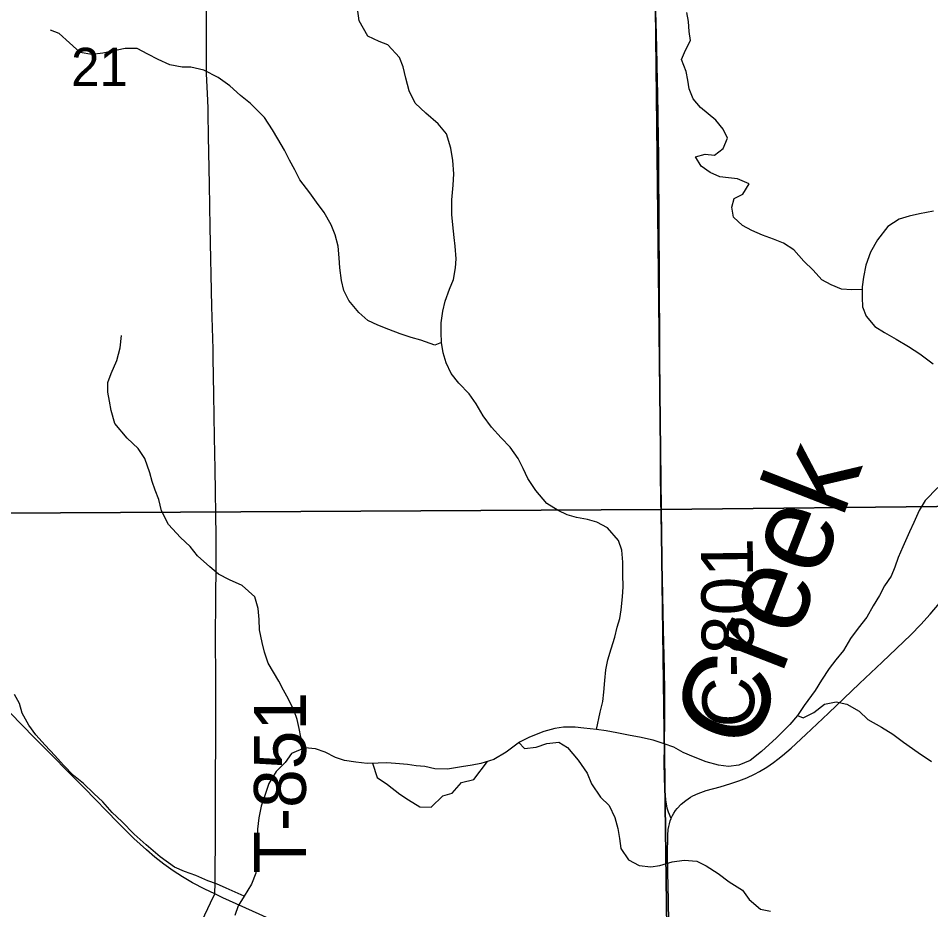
# Model space of a CAD drawing. Extents: x 1874609 to 2204689, y 815661 to 1281160.
# Drawn here: x 2025118 to 2030390, y 1065160 to 1070308 of the extents above; entities that cross this region are included whole.
import ezdxf

# ---------------------------------------------------------------- set-up
doc = ezdxf.new("R2010")
doc.units = 0
for name, color, linetype in [('GM_X_County_Road', 7, 'Continuous'), ('GM_X_County_Road_Text', 7, 'Continuous'), ('GM_X_Minor_River', 7, 'Continuous'), ('GM_X_Minor_River_Text', 7, 'Continuous'), ('GM_X_Section', 7, 'Continuous'), ('GM_X_Section_Text', 7, 'Continuous'), ('GM_X_State_Route', 7, 'Continuous'), ('GM_X_Township_Road', 7, 'Continuous'), ('GM_X_Township_Road_Text', 7, 'Continuous')]:
    doc.layers.add(name, color=color, linetype=linetype)

msp = doc.modelspace()

# ---------------------------------------------------------------- linework, layer by layer
at = {"layer": 'GM_X_County_Road'}
msp.add_lwpolyline([(2028889.9, 1065686.4), (2028876.2, 1065723.5), (2028867.4, 1065747), (2028860.1, 1065795.2), (2028855.4, 1065844.3), (2028852.1, 1065909.8), (2028851.2, 1066024.2), (2028851.9, 1066089.5), (2028854.2, 1066286.3), (2028853.4, 1066417.4), (2028851.6, 1066548.6), (2028847, 1066777.8), (2028840.5, 1067072.6), (2028835, 1067318.4), (2028832.8, 1067449.6), (2028831.5, 1067515.1), (2028829.6, 1067695.3), (2028828.4, 1067810.1), (2028828, 1068023.4), (2028827.4, 1068187.4), (2028825.8, 1068318.6), (2028824.6, 1068499), (2028823.3, 1068712.3), (2028823, 1068892.8), (2028822.2, 1069040.3), (2028821, 1069204.3), (2028819.8, 1069384.8), (2028819.3, 1069515.9), (2028817.9, 1069614.3), (2028815.1, 1069745.3), (2028812.9, 1069876.5), (2028811.7, 1069942), (2028807.4, 1070138.4), (2028803.4, 1070285.9), (2028800.7, 1070400.8)], dxfattribs=at)
at = {"layer": 'GM_X_Minor_River'}
for points in [[(2028459.2, 1066201.1), (2028480.4, 1066301.6), (2028496, 1066362), (2028501.5, 1066416.2), (2028507, 1066484.5), (2028512.5, 1066544.7), (2028524.1, 1066603), (2028543.6, 1066667.3), (2028565.1, 1066733.8), (2028578.7, 1066792.1), (2028594.3, 1066842.3), (2028601.9, 1066892.6), (2028609.3, 1066966.9), (2028612.9, 1067025.1), (2028612.3, 1067095.3), (2028611.7, 1067167.6), (2028605.1, 1067235.8), (2028586.6, 1067291.8), (2028523.8, 1067365.6), (2028461.4, 1067397.2), (2028407.1, 1067412.9), (2028342.8, 1067424.5), (2028290.5, 1067440.1), (2028238.2, 1067465.8), (2028171.6, 1067505.5), (2028108.8, 1067581.3), (2028062.1, 1067651.1), (2028035.6, 1067707.1), (2028007, 1067765.1), (2027960.3, 1067831), (2027907.7, 1067884.8), (2027853.1, 1067946.6), (2027804.4, 1068012.5), (2027763.7, 1068082.4), (2027723.1, 1068138.3), (2027664.4, 1068200.1), (2027619.8, 1068255.9), (2027591.3, 1068317.9), (2027572.7, 1068376), (2027564.2, 1068436.1), (2027561.7, 1068494.3), (2027561.3, 1068548.5), (2027570.8, 1068616.8), (2027584.3, 1068675.1), (2027609.8, 1068743.5), (2027633.4, 1068799.9), (2027644.9, 1068866.2), (2027648.5, 1068918.4), (2027641.9, 1068992.6), (2027637.5, 1069042.7), (2027628.9, 1069114.9), (2027624.3, 1069175.1), (2027623.6, 1069259.4), (2027631, 1069343.7), (2027634.5, 1069409.9), (2027629.8, 1069486.2), (2027617.2, 1069558.3), (2027592.4, 1069640.4), (2027543.8, 1069698.2), (2027473.1, 1069759.9), (2027412.5, 1069817.7), (2027377.8, 1069889.7), (2027357.1, 1069961.8), (2027342.5, 1070027.9), (2027322, 1070081.9), (2027253.2, 1070155.6), (2027202.9, 1070173.3), (2027138.5, 1070205), (2027087.6, 1070292.9), (2027079, 1070365.1)], [(2029994.4, 1068741.4), (2029934.3, 1068740), (2029874.3, 1068744.4), (2029814.3, 1068768.9), (2029760.3, 1068797.3), (2029710.6, 1068853.8), (2029656.8, 1068906.3), (2029599, 1068970.9), (2029539.1, 1069009.4), (2029481.1, 1069031.8), (2029419.2, 1069056.3), (2029357.2, 1069082.8), (2029303.2, 1069111.3), (2029251.4, 1069159.7), (2029241.7, 1069218), (2029254, 1069268.1), (2029304.2, 1069291.8), (2029340.6, 1069351.8), (2029274.6, 1069380.3), (2029222.6, 1069386.6), (2029172.5, 1069393), (2029116.6, 1069417.4), (2029064.7, 1069453.9), (2029030.9, 1069508.3), (2029087.1, 1069523.9), (2029141.1, 1069517.6), (2029191.4, 1069555.4), (2029215.8, 1069615.4), (2029192, 1069667.7), (2029148.2, 1069720.2), (2029060.5, 1069793), (2029018.7, 1069843.4), (2028994.9, 1069899.7), (2028987.2, 1069949.9), (2028977.4, 1070000.2), (2028949.8, 1070070.6), (2028974.1, 1070124.6), (2029002.4, 1070180.6), (2028994.7, 1070230.8), (2028991, 1070289), (2028981.3, 1070341.2)], [(2027564.2, 1068436.1), (2027526.2, 1068419.8), (2027443.7, 1068449.3), (2027389.4, 1068464.9), (2027325.1, 1068486.5), (2027258.7, 1068510.1), (2027196.3, 1068535.8), (2027137.9, 1068563.4), (2027085.4, 1068609.2), (2027028.6, 1068679), (2027000.1, 1068735), (2026985.6, 1068793.1), (2026976.9, 1068867.2), (2026972.4, 1068925.4), (2026965.9, 1068991.6), (2026949.3, 1069057.7), (2026926.8, 1069115.7), (2026886.1, 1069185.7), (2026841.4, 1069245.5), (2026802.9, 1069299.4), (2026746.1, 1069375.3), (2026715.5, 1069433.2), (2026685, 1069489.2), (2026656.4, 1069547.2), (2026617.8, 1069611.1), (2026587.3, 1069663.1), (2026540.5, 1069735), (2026459.6, 1069816.6), (2026403.1, 1069862.4), (2026340.4, 1069918.1), (2026273.9, 1069965.8), (2026191.3, 1070009.3), (2026114.9, 1070024.8), (2026064.7, 1070026.4), (2025994.4, 1070040), (2025926, 1070069.6), (2025867.5, 1070101.2), (2025805.1, 1070132.9), (2025736.9, 1070134.4), (2025606.7, 1070107.3), (2025542.6, 1070098.8), (2025476.3, 1070110.4), (2025413.6, 1070166.1), (2025355, 1070219.8), (2025304.7, 1070239.5)], [(2030406.4, 1069193.7), (2030326.3, 1069179.1), (2030266.3, 1069164.6), (2030208.2, 1069148.1), (2030142.4, 1069105.5), (2030082.8, 1069028.8), (2030043.3, 1068958.2), (2030015.8, 1068881.8), (2030002.4, 1068813.4), (2029994.8, 1068757.2), (2029993.3, 1068695), (2029995.7, 1068640.8), (2030018.2, 1068586.8), (2030066.9, 1068529), (2030123.3, 1068493.3), (2030189.8, 1068455.6), (2030262.4, 1068412), (2030326.9, 1068370.3), (2030403.6, 1068312.7)], [(2026775.1, 1066094.3), (2026750.5, 1066156.3), (2026742.1, 1066206.4), (2026729.6, 1066258.5), (2026713.1, 1066308.5), (2026680.5, 1066376.5), (2026650, 1066428.5), (2026623.4, 1066480.5), (2026562.4, 1066584.4), (2026541.8, 1066646.4), (2026527.3, 1066702.5), (2026512.7, 1066776.7), (2026510.2, 1066836.9), (2026503.7, 1066899), (2026485, 1066967.1), (2026412.3, 1067032.8), (2026339.8, 1067064.4), (2026275.3, 1067098), (2026224.9, 1067139.8), (2026154.1, 1067203.5), (2026111.5, 1067257.3), (2026055, 1067309.1), (2025986.1, 1067384.8), (2025945.4, 1067462.8), (2025930.8, 1067528.9), (2025910.3, 1067583), (2025891.8, 1067633), (2025879.4, 1067683.1), (2025850.6, 1067765.2), (2025812, 1067823.1), (2025747.3, 1067882.8), (2025676.4, 1067968.6), (2025655.8, 1068042.7), (2025645.3, 1068096.8), (2025636.8, 1068148.9), (2025636.4, 1068205.1), (2025656, 1068257.4), (2025687.5, 1068331.9), (2025706.9, 1068404.3), (2025714.4, 1068476.6)], [(2030431.6, 1067598.5), (2030357.9, 1067523.7), (2030324.3, 1067465.3), (2030292.8, 1067396.8), (2030267.2, 1067342.4), (2030229.8, 1067255.9), (2030202.2, 1067193.4), (2030182.6, 1067139.1), (2030160.9, 1067086.8), (2030123.3, 1067030.3), (2030093.7, 1066973.9), (2030058, 1066915.4), (2030020.5, 1066848.9), (2029970.8, 1066786.3), (2029927.2, 1066725.8), (2029885.6, 1066657.3), (2029842, 1066602.8), (2029804.3, 1066552.3), (2029758.7, 1066485.7), (2029723.1, 1066425.3), (2029659.6, 1066338.5), (2029619.9, 1066282)], [(2026423.1, 1065238.7), (2026320.4, 1065284.1), (2026264, 1065309.7), (2026213.7, 1065327.4), (2026145.3, 1065357), (2026078.9, 1065380.6), (2026020.5, 1065406.3), (2025937.7, 1065465.9), (2025856.9, 1065535.5), (2025788.2, 1065597.2), (2025717.4, 1065668.9), (2025660.8, 1065720.7), (2025606.2, 1065782.5), (2025555.6, 1065830.3), (2025495, 1065888.1), (2025438.4, 1065935.8), (2025379.7, 1065995.6), (2025329.1, 1066051.4), (2025274.5, 1066111.2), (2025219.8, 1066169), (2025179.3, 1066224.9), (2025140.6, 1066294.8), (2025126.1, 1066350.9), (2025097.5, 1066402.9)], [(2029619.9, 1066282), (2029654.1, 1066268.3), (2029714.1, 1066298.8), (2029775.9, 1066347.4), (2029844, 1066359.9), (2029906.3, 1066346.4), (2029976.8, 1066306.7), (2030027.3, 1066258.9), (2030105.9, 1066213.4), (2030170.5, 1066173.7), (2030233, 1066128), (2030317.7, 1066068.4), (2030394.4, 1066016.8)], [(2029619.9, 1066282), (2029576.2, 1066229.5), (2029498.6, 1066152.7), (2029413, 1066073.8), (2029347.3, 1066021.1), (2029281.3, 1065994.5), (2029221.2, 1065988), (2029164.9, 1065995.6), (2029092.6, 1066013.2), (2029020.1, 1066042.7), (2028959.7, 1066068.4), (2028905.3, 1066098.1), (2028851, 1066117.8), (2028786.7, 1066139.3), (2028708.3, 1066156.8), (2028654, 1066166.5), (2028577.7, 1066181.9), (2028515.4, 1066193.5), (2028459.2, 1066201.1), (2028386.9, 1066208.6), (2028336.7, 1066214.3), (2028268.5, 1066213.8), (2028218.4, 1066207.4), (2028154.4, 1066188.8), (2028072.4, 1066156.1), (2028014.5, 1066127.6), (2027936.7, 1066070.8), (2027866.8, 1066028.1), (2027790.8, 1066003.5), (2027740.7, 1065995.1), (2027678.6, 1065984.6), (2027598.5, 1065971.9), (2027524.3, 1065973.4), (2027468, 1065987), (2027417.8, 1065990.7), (2027367.6, 1065998.3), (2027297.4, 1066003.8), (2027247.2, 1066007.5), (2027197, 1066007.1), (2027134.9, 1066004.6), (2027068.6, 1066012.2), (2027004.3, 1066021.7), (2026952, 1066039.4), (2026891.6, 1066069), (2026835.3, 1066088.7), (2026775.1, 1066094.3), (2026697.1, 1066061.6), (2026661.4, 1066011.1), (2026607.7, 1065958.6), (2026566.1, 1065888), (2026538.7, 1065807.5), (2026521.1, 1065757.2), (2026507.6, 1065690.9), (2026500.1, 1065624.6), (2026496.7, 1065546.3), (2026495.2, 1065492.1), (2026493.7, 1065429.9), (2026490.2, 1065371.6), (2026466.6, 1065307.2), (2026423.1, 1065238.7), (2026389.4, 1065182.2), (2026369.8, 1065125.9)], [(2028010.8, 1066124.9), (2028042.8, 1066091.7), (2028111, 1066098.2), (2028173, 1066120.7), (2028241.1, 1066127.3), (2028291.5, 1066097.5), (2028354.3, 1066023.7), (2028405.1, 1065947.8), (2028429.7, 1065887.8), (2028482.5, 1065809.9), (2028533, 1065762.1), (2028565.7, 1065692.1), (2028582.2, 1065628.1), (2028592.7, 1065571.9), (2028599.2, 1065513.8), (2028643.9, 1065447.9), (2028706.3, 1065416.2), (2028772.6, 1065406.7), (2028824.7, 1065415.1), (2028896.7, 1065435.7), (2028964.9, 1065446.3), (2029039.1, 1065440.8), (2029093.5, 1065413.1), (2029162.1, 1065369.4), (2029226.7, 1065321.8), (2029303.3, 1065272.2), (2029341.8, 1065218.2), (2029406.5, 1065162.6), (2029464.8, 1065150.9)], [(2027165.9, 1066005.8), (2027191.7, 1065922.8), (2027252.2, 1065883.1), (2027322.9, 1065827.4), (2027373.3, 1065793.7), (2027437.8, 1065754), (2027504, 1065752.5), (2027571.7, 1065817.2), (2027625.7, 1065833.7), (2027679.4, 1065894.3), (2027751.4, 1065912.9), (2027828.6, 1066015.8)]]:
    msp.add_lwpolyline(points, dxfattribs=at)
at = {"layer": 'GM_X_Section'}
for points in [[(2028774, 1072757.7), (2034097, 1072800.8), (2034142, 1067529.9), (2028833.1, 1067470.8)], [(2028774, 1072757.7), (2028833.1, 1067470.8), (2023626.2, 1067442), (2023577.1, 1072706.8)], [(2034142, 1067529.9), (2034181.1, 1062215), (2028904.1, 1062206), (2028833.1, 1067470.8)], [(2028833.1, 1067470.8), (2028904.1, 1062206), (2023667.3, 1062153.1), (2023626.2, 1067442)]]:
    msp.add_lwpolyline(points, close=True, dxfattribs=at)
at = {"layer": 'GM_X_State_Route'}
for points in [[(2029506.3, 1066029), (2029534.6, 1066050.8), (2029584.6, 1066093.4), (2029669.4, 1066171.4), (2029800.3, 1066295.6), (2029978.1, 1066465.5), (2030109.5, 1066589.1), (2030275.3, 1066747.9), (2030332.5, 1066806.5), (2030387.7, 1066867), (2030440.3, 1066929.6), (2030490.3, 1066994.4), (2030566.9, 1067100.8), (2030695.8, 1067286)], [(2028076.7, 1064421.3), (2027928.1, 1064487.6), (2027764, 1064562.6), (2027599.7, 1064637.3), (2027480.4, 1064692), (2027286.7, 1064781.3), (2027092.3, 1064868.6), (2026853.8, 1064978.3), (2026510, 1065134), (2026300.8, 1065228.8), (2026253.8, 1065251.1), (2026197.1, 1065278), (2026124.7, 1065315.9), (2026068.3, 1065349), (2026013.3, 1065384.5), (2025960, 1065422.4), (2025908.4, 1065462.6), (2025858.8, 1065505.3), (2025786.9, 1065572.1), (2025693.6, 1065664.4), (2025498.7, 1065863.9), (2025221.8, 1066143.8), (2025130.2, 1066237.6), (2025039.1, 1066331.2)], [(2028876.9, 1065083.5), (2028875.5, 1065213.6), (2028871.5, 1065377.3), (2028870, 1065475.8), (2028872.1, 1065590.7), (2028874.3, 1065623.8), (2028876.7, 1065640.2), (2028880.2, 1065656.5), (2028884.8, 1065672.6), (2028889.9, 1065686.4), (2028890.7, 1065688.4), (2028897.6, 1065703.6), (2028905.9, 1065718.3), (2028915.2, 1065732.3), (2028925.8, 1065745.3), (2028949.3, 1065769.1), (2028974.9, 1065790.3), (2029002.3, 1065809.3), (2029016.7, 1065817.6), (2029046.9, 1065831.7), (2029093.7, 1065848.2), (2029173, 1065870.1), (2029235.9, 1065888), (2029282.3, 1065903.7), (2029327.7, 1065921.8), (2029372.2, 1065942.3), (2029400.9, 1065957.6), (2029442.5, 1065983.2), (2029482.8, 1066010.9), (2029506.3, 1066029)]]:
    msp.add_lwpolyline(points, dxfattribs=at)
at = {"layer": 'GM_X_Township_Road'}
for points in [[(2026253.8, 1065251.1), (2026256.9, 1065314.4), (2026256.7, 1065380), (2026258.3, 1065560.5), (2026258.4, 1065757.4), (2026259.4, 1066298.9), (2026259.2, 1066446.5), (2026258.2, 1066774.3), (2026259, 1066905.6), (2026259.1, 1066971.2), (2026262.3, 1067135.3), (2026261.7, 1067316.1), (2026256.9, 1067704.3), (2026251.9, 1067889.2), (2026248.3, 1068134.8), (2026245, 1068347.6), (2026244.3, 1068396.8), (2026237.4, 1068642.8), (2026228, 1069102), (2026222.9, 1069348.1), (2026217.6, 1069627), (2026216.6, 1069758.2), (2026215, 1069791), (2026211.4, 1069872.9), (2026206.8, 1069987.4), (2026205.8, 1070036.5), (2026206.1, 1070085.7), (2026206.5, 1070151.3), (2026206.1, 1070265.9), (2026205.4, 1070413.3)], [(2026180.4, 1065096.8), (2026229.8, 1065200.6), (2026253.8, 1065251.1)]]:
    msp.add_lwpolyline(points, dxfattribs=at)

# ---------------------------------------------------------------- texts
at = {"layer": 'GM_X_County_Road_Text'}
msp.add_text('C-801', height=300, rotation=90.5496, dxfattribs=at).set_placement((2029372.3, 1066214.9))
at = {"layer": 'GM_X_Minor_River_Text'}
msp.add_text('Creek', height=500.12, rotation=68.7551, dxfattribs=at).set_placement((2029352.2, 1066060.8))
at = {"layer": 'GM_X_Section_Text'}
msp.add_text('21', height=221, rotation=0, dxfattribs=at).set_placement((2025423.5, 1069916.4))
at = {"layer": 'GM_X_Township_Road_Text'}
msp.add_text('T-851', height=300, rotation=90, dxfattribs=at).set_placement((2026780.2, 1065369.3))

doc.saveas('drawing.dxf')
